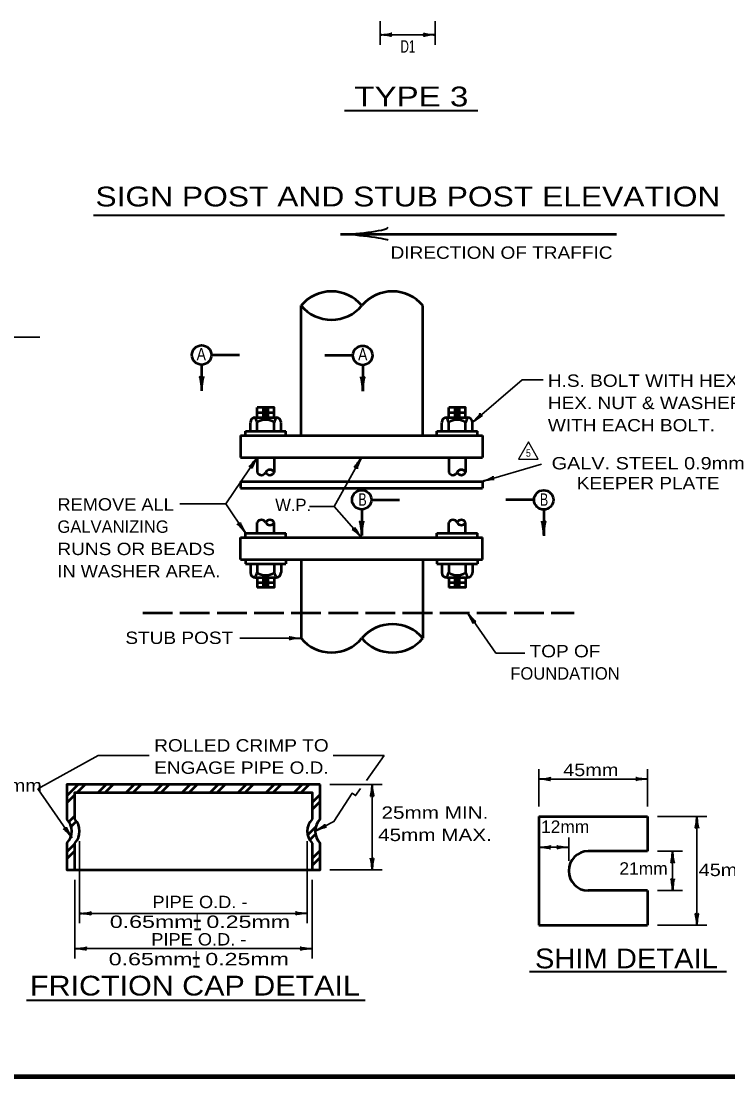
# Model space of a CAD drawing. Extents: x 11 to 867, y -284 to 260.
# Drawn here: x 258 to 429.3, y -272.1 to -16.1 of the extents above; entities that cross this region are included whole.
import ezdxf
from ezdxf.enums import TextEntityAlignment as Align

# ---------------------------------------------------------------- set-up
doc = ezdxf.new("R2010")
doc.units = 0
doc.header["$LTSCALE"] = 1.2
doc.linetypes.add('LONG_DASHED', pattern=[7.5, 6, -1.5])
doc.layers.add('1', color=7, linetype='Continuous', lineweight=53)

msp = doc.modelspace()

# ---------------------------------------------------------------- linework, layer by layer
at = {"layer": '1', "lineweight": 35}
for p, q in [((345.013, -16.126), (345.013, -21.85)), ((358.377, -16.126), (358.377, -21.85)), ((345.013, -19.45), (358.377, -19.45)), ((232.558, -92.754), (262.538, -92.754)), ((367.425, -113.403), (379.445, -103.077)), ((379.445, -103.077), (384.523, -103.077)), ((369.825, -127.715), (384.143, -123.529)), ((307.595, -133.179), (296.457, -133.179)), ((333.905, -133.811), (327.875, -133.811)), ((366.273, -159.583), (373.101, -169.399)), ((325.855, -165.759), (311.025, -165.759)), ((373.101, -169.399), (380.141, -169.399)), ((262.06, -202.238), (276.645, -194.196)), ((276.645, -194.196), (289.043, -194.196)), ((333.644, -194.196), (345.983, -194.196)), ((341.7, -200.214), (345.983, -194.196)), ((383.486, -206.545), (383.486, -197.489)), ((409.886, -206.545), (409.886, -197.489)), ((332.874, -201.194), (345.502, -201.194)), ((343.102, -201.194), (343.102, -221.938)), ((383.486, -199.889), (409.886, -199.889)), ((270.264, -214.108), (262.06, -202.238)), ((412.286, -208.945), (424.216, -208.945)), ((421.816, -208.945), (421.816, -235.345)), ((272.182, -214.926), (272.182, -234.868)), ((327.382, -214.926), (327.382, -234.868)), ((390.758, -219.745), (390.758, -214.039)), ((390.758, -216.439), (383.486, -216.439)), ((412.286, -217.345), (418.336, -217.345)), ((415.936, -217.345), (415.936, -226.945)), ((332.874, -221.938), (345.502, -221.938)), ((271.01, -224.338), (271.01, -243.414)), ((328.554, -224.338), (328.554, -243.414)), ((412.286, -226.945), (418.336, -226.945)), ((272.182, -232.468), (327.382, -232.468)), ((412.286, -235.345), (424.216, -235.345)), ((271.01, -241.014), (328.554, -241.014))]:
    msp.add_line(p, q, dxfattribs=at)
at = {"layer": '1', "lineweight": 40}
for p, q in [((336.358, -37.837), (368.69, -37.837)), ((275.564, -63.195), (428.48, -63.195)), ((381.209, -246.561), (428.965, -246.561)), ((259.342, -253.484), (341.423, -253.484))]:
    msp.add_line(p, q, dxfattribs=at)
at = {"layer": '1'}
for p, q in [((335.435, -67.761), (402.333, -67.761)), ((325.855, -116.557), (325.855, -85.095)), ((355.407, -116.557), (355.407, -85.095)), ((304.117, -97.074), (310.933, -97.074)), ((338.457, -97.166), (331.641, -97.166)), ((301.769, -99.423), (301.769, -105.758)), ((340.804, -99.516), (340.804, -105.851)), ((314.769, -112.203), (319.809, -112.203)), ((315.249, -111.003), (319.329, -111.003)), ((316.449, -110.403), (318.129, -110.403)), ((316.449, -111.603), (318.129, -111.603)), ((361.185, -112.203), (366.225, -112.203)), ((361.665, -111.003), (365.745, -111.003)), ((362.865, -110.403), (364.545, -110.403)), ((362.865, -111.603), (364.545, -111.603)), ((313.569, -115.533), (313.569, -113.403)), ((315.249, -115.533), (315.249, -113.403)), ((319.329, -115.533), (319.329, -113.403)), ((321.009, -115.533), (321.009, -113.403)), ((359.985, -115.533), (359.985, -113.403)), ((361.665, -115.533), (361.665, -113.403)), ((365.745, -115.533), (365.745, -113.403)), ((367.425, -115.533), (367.425, -113.403)), ((311.169, -116.557), (369.825, -116.557)), ((311.169, -116.557), (311.169, -121.937)), ((312.369, -115.533), (322.209, -115.533)), ((312.369, -116.557), (312.369, -115.533)), ((322.209, -116.557), (322.209, -115.533)), ((358.785, -115.533), (368.625, -115.533)), ((358.785, -116.557), (358.785, -115.533)), ((368.625, -116.557), (368.625, -115.533)), ((369.825, -116.557), (369.825, -121.937)), ((311.169, -121.937), (369.825, -121.937)), ((315.249, -121.937), (315.249, -125.537)), ((319.329, -121.937), (319.329, -125.537)), ((361.665, -121.937), (361.665, -125.537)), ((365.745, -121.937), (365.745, -125.537)), ((311.169, -127.715), (369.825, -127.715)), ((311.169, -127.715), (311.169, -129.341)), ((369.825, -127.715), (369.825, -129.341)), ((311.169, -129.341), (369.825, -129.341)), ((342.921, -132.169), (349.737, -132.169)), ((382.345, -132.209), (375.529, -132.209)), ((340.573, -134.519), (340.573, -140.853)), ((384.693, -134.559), (384.693, -140.894)), ((315.249, -140.269), (315.249, -137.693)), ((319.329, -140.269), (319.329, -137.693)), ((361.665, -140.269), (361.665, -137.693)), ((365.745, -140.269), (365.745, -137.693)), ((312.369, -140.269), (322.209, -140.269)), ((312.369, -141.293), (312.369, -140.269)), ((322.209, -141.293), (322.209, -140.269)), ((358.785, -140.269), (368.625, -140.269)), ((358.785, -141.293), (358.785, -140.269)), ((368.625, -141.293), (368.625, -140.269)), ((311.169, -141.293), (369.825, -141.293)), ((311.169, -146.673), (311.169, -141.293)), ((369.825, -146.673), (369.825, -141.293)), ((311.169, -146.673), (369.825, -146.673)), ((312.369, -146.673), (312.369, -147.697)), ((312.369, -147.697), (322.209, -147.697)), ((313.569, -147.697), (313.569, -149.827)), ((315.249, -147.697), (315.249, -149.827)), ((319.329, -147.697), (319.329, -149.827)), ((321.009, -147.697), (321.009, -149.827)), ((322.209, -146.673), (322.209, -147.697)), ((325.855, -146.673), (325.855, -165.759)), ((355.407, -146.673), (355.407, -165.759)), ((358.785, -146.673), (358.785, -147.697)), ((358.785, -147.697), (368.625, -147.697)), ((359.985, -147.697), (359.985, -149.827)), ((361.665, -147.697), (361.665, -149.827)), ((365.745, -147.697), (365.745, -149.827)), ((367.425, -147.697), (367.425, -149.827)), ((368.625, -146.673), (368.625, -147.697)), ((314.769, -151.027), (319.809, -151.027)), ((315.249, -152.227), (319.329, -152.227)), ((316.449, -151.627), (318.129, -151.627)), ((316.449, -152.827), (318.129, -152.827)), ((361.185, -151.027), (366.225, -151.027)), ((361.665, -152.227), (365.745, -152.227)), ((362.865, -151.627), (364.545, -151.627)), ((362.865, -152.827), (364.545, -152.827)), ((269.09, -203.942), (271.838, -201.194)), ((271.615, -203.114), (273.535, -201.194)), ((276.706, -203.114), (278.626, -201.194)), ((278.404, -203.114), (280.324, -201.194)), ((283.495, -203.114), (285.415, -201.194)), ((285.192, -203.114), (287.112, -201.194)), ((290.283, -203.114), (292.203, -201.194)), ((291.98, -203.114), (293.9, -201.194)), ((297.071, -203.114), (298.991, -201.194)), ((298.768, -203.114), (300.688, -201.194)), ((303.859, -203.114), (305.779, -201.194)), ((305.556, -203.114), (307.476, -201.194)), ((310.648, -203.114), (312.567, -201.194)), ((312.345, -203.114), (314.265, -201.194)), ((317.436, -203.114), (319.356, -201.194)), ((319.133, -203.114), (321.053, -201.194)), ((324.224, -203.114), (326.144, -201.194)), ((325.921, -203.114), (327.841, -201.194)), ((330.474, -209.586), (330.474, -201.194)), ((269.09, -205.639), (271.01, -203.719)), ((328.554, -205.572), (330.474, -203.652)), ((328.554, -207.269), (330.474, -205.349)), ((269.585, -210.235), (271.01, -208.811)), ((383.486, -208.945), (409.886, -208.945)), ((383.486, -208.945), (383.486, -235.345)), ((409.886, -208.945), (409.886, -217.345)), ((270.104, -211.413), (271.42, -210.097)), ((327.489, -213.425), (329.444, -211.471)), ((327.961, -214.651), (329.366, -213.246)), ((269.09, -217.519), (271.01, -215.599)), ((269.09, -219.216), (271.01, -217.296)), ((328.554, -219.149), (330.474, -217.229)), ((409.886, -217.345), (395.498, -217.345)), ((328.554, -220.846), (330.474, -218.926)), ((271.01, -221.938), (328.554, -221.938)), ((409.886, -226.945), (395.498, -226.945)), ((409.886, -226.945), (409.886, -235.345)), ((383.486, -235.345), (409.886, -235.345))]:
    msp.add_line(p, q, dxfattribs=at)
at = {"layer": '1', "linetype": 'LONG_DASHED'}
msp.add_line((287.495, -159.609), (392.105, -159.609), dxfattribs=at)
at = {"layer": '1', "lineweight": 158}
msp.add_line((860.008, -272.101), (68.408, -272.101), dxfattribs=at)
at = {"layer": '1'}
for points in [[(319.329, -112.203), (319.329, -109.803), (315.249, -109.803)], [(315.249, -112.203), (315.249, -111.003), (315.249, -109.803)], [(365.745, -112.203), (365.745, -109.803), (361.665, -109.803)], [(361.665, -112.203), (361.665, -111.003), (361.665, -109.803)], [(319.329, -151.027), (319.329, -153.427), (315.249, -153.427)], [(315.249, -151.027), (315.249, -152.227), (315.249, -153.427)], [(365.745, -151.027), (365.745, -153.427), (361.665, -153.427)], [(361.665, -151.027), (361.665, -152.227), (361.665, -153.427)], [(330.474, -201.194), (269.09, -201.194), (269.09, -209.586)], [(271.01, -209.586), (271.01, -203.114), (328.554, -203.114), (328.554, -209.586)], [(269.09, -215.466), (269.09, -221.938), (271.01, -221.938), (271.01, -215.466)], [(328.554, -215.466), (328.554, -221.938), (330.474, -221.938), (330.474, -215.466)]]:
    msp.add_lwpolyline(points, dxfattribs=at)
at = {"layer": '1', "lineweight": 25}
msp.add_lwpolyline([(380.978, -118.162), (378.578, -122.319), (383.378, -122.319)], close=True, dxfattribs=at)
at = {"layer": '1', "lineweight": 35}
for points in [[(315.249, -121.937), (307.595, -133.179), (312.369, -140.269)], [(340.497, -121.937), (333.905, -133.811), (340.497, -141.293)], [(329.302, -212.526), (333.85, -210.192), (338.238, -203.324), (339.088, -203.89), (340.308, -202.172)]]:
    msp.add_lwpolyline(points, dxfattribs=at)
at = {"layer": '1'}
for centre in [(301.768, -97.075), (340.805, -97.167), (340.572, -132.17), (384.694, -132.21)]:
    msp.add_circle(centre, 2.349, dxfattribs=at)
for centre, radius, start, end in [((333.243, -91.313), 9.656, 40.08466, 139.91534), ((348.019, -91.313), 9.656, 40.08466, 139.91534), ((333.243, -78.877), 9.656, 220.08466, 319.91534), ((314.815, -113.449), 1.247, 92.13194, 177.86806), ((301.279, -118.295), 14.802, 19.29918, 24.30364), ((333.299, -118.295), 14.802, 155.69636, 160.70082), ((319.762, -113.449), 1.247, 2.13194, 87.86806), ((361.231, -113.449), 1.247, 92.13194, 177.86806), ((347.695, -118.295), 14.802, 19.29918, 24.30364), ((379.715, -118.295), 14.802, 155.69636, 160.70082), ((366.178, -113.449), 1.247, 2.13194, 87.86806), ((317.289, -116.372), 3.602, 55.5053, 124.4947), ((363.705, -116.372), 3.602, 55.5053, 124.4947), ((318.309, -126.023), 1.13, 25.46796, 154.53204), ((364.725, -126.023), 1.13, 25.46796, 154.53204), ((316.269, -125.051), 1.13, 205.46796, 334.53204), ((318.309, -125.051), 1.13, 205.46796, 334.53204), ((362.685, -125.051), 1.13, 205.46796, 334.53204), ((364.725, -125.051), 1.13, 205.46796, 334.53204), ((316.269, -138.179), 1.13, 25.46796, 154.53204), ((318.309, -138.179), 1.13, 25.46796, 154.53204), ((318.309, -137.207), 1.13, 205.46796, 334.53204), ((362.685, -138.179), 1.13, 25.46796, 154.53204), ((364.725, -138.179), 1.13, 25.46796, 154.53204), ((364.725, -137.207), 1.13, 205.46796, 334.53204), ((314.815, -149.781), 1.247, 182.13194, 267.86806), ((301.279, -144.935), 14.802, 335.69636, 340.70082), ((317.289, -146.858), 3.602, 235.5053, 304.4947), ((333.299, -144.935), 14.802, 199.29918, 204.30364), ((319.762, -149.781), 1.247, 272.13194, 357.86806), ((361.231, -149.781), 1.247, 182.13194, 267.86806), ((347.695, -144.935), 14.802, 335.69636, 340.70082), ((363.705, -146.858), 3.602, 235.5053, 304.4947), ((379.715, -144.935), 14.802, 199.29918, 204.30364), ((366.178, -149.781), 1.247, 272.13194, 357.86806), ((348.019, -171.977), 9.656, 40.08466, 139.91534), ((333.243, -159.541), 9.656, 220.08466, 319.91534), ((348.019, -159.541), 9.656, 220.08466, 319.91534), ((265.99, -212.526), 4.272, 316.51802, 43.48198), ((267.91, -212.526), 4.272, 316.51802, 43.48198), ((331.654, -212.526), 4.272, 136.51802, 223.48198), ((333.574, -212.526), 4.272, 136.51802, 223.48198), ((395.557, -222.145), 4.8, 90.71094, 269.28906)]:
    msp.add_arc(centre, radius, start, end, dxfattribs=at)
at = {"layer": '1', "lineweight": 40}
for centre, major_axis, ratio, start_param, end_param in [((346.133, -19.661), (-1.756, 0.176), 0.07063, 3.1407148, 5.41811), ((346.133, -19.661), (-1.756, 0.176), 0.07063, 3.1407148, 5.41811), ((346.104, -19.173), (-1.786, -0.156), 0.122415, 0.8963533, 3.1415927), ((346.104, -19.173), (-1.786, -0.156), 0.122415, 0.8963533, 3.1415927), ((357.286, -19.726), (1.786, 0.156), 0.122415, 0.8963533, 3.1415927), ((357.256, -19.238), (1.756, -0.176), 0.07063, 3.1407148, 5.41811), ((339.835, -66.688), (-7.143, -0.625), 0.122415, 0.8963533, 3.1415927), ((339.953, -68.639), (-7.026, 0.703), 0.07063, 3.1407148, 5.41811), ((301.434, -104.432), (0.19, -2.17), 0.122415, 0.8963533, 3.1415927), ((302.026, -104.397), (-0.213, -2.134), 0.07063, 3.1407148, 5.41811), ((340.547, -104.489), (0.213, -2.134), 0.07063, 0.8650754, 3.1424706), ((341.14, -104.525), (-0.19, -2.17), 0.122415, 3.1415927, 5.386832), ((368.072, -112.482), (-1.253, -1.282), 0.122415, 0.8963533, 3.1415927), ((368.072, -112.482), (-1.253, -1.282), 0.122415, 0.8963533, 3.1415927), ((368.413, -112.833), (-1.447, -1.011), 0.07063, 3.1407148, 5.41811), ((368.413, -112.833), (-1.447, -1.011), 0.07063, 3.1407148, 5.41811), ((314.443, -122.744), (1.134, 1.353), 0.07063, 3.1407148, 5.41811), ((314.443, -122.744), (1.134, 1.353), 0.07063, 3.1407148, 5.41811), ((314.863, -122.994), (0.876, 1.564), 0.122415, 0.8963533, 3.1415927), ((314.863, -122.994), (0.876, 1.564), 0.122415, 0.8963533, 3.1415927), ((339.768, -122.814), (1.006, 1.45), 0.07063, 3.1407148, 5.41811), ((339.768, -122.814), (1.006, 1.45), 0.07063, 3.1407148, 5.41811), ((340.209, -123.025), (0.73, 1.637), 0.122415, 0.8963533, 3.1415927), ((340.209, -123.025), (0.73, 1.637), 0.122415, 0.8963533, 3.1415927), ((370.795, -127.143), (-1.67, -0.651), 0.122415, 0.8963533, 3.1415927), ((370.96, -127.604), (-1.735, -0.324), 0.07063, 3.1407148, 5.41811), ((311.53, -139.518), (1.127, -1.394), 0.122415, 0.8963533, 3.1415927), ((311.918, -139.221), (0.835, -1.555), 0.07063, 3.1407148, 5.41811), ((340.238, -139.528), (0.19, -2.17), 0.122415, 0.8963533, 3.1415927), ((340.83, -139.492), (-0.213, -2.134), 0.07063, 3.1407148, 5.41811), ((384.436, -139.532), (0.213, -2.134), 0.07063, 0.8650754, 3.1424706), ((385.028, -139.568), (-0.19, -2.17), 0.122415, 3.1415927, 5.386832), ((339.568, -140.657), (1.298, -1.237), 0.122415, 0.8963533, 3.1415927), ((339.915, -140.312), (1.029, -1.434), 0.07063, 3.1407148, 5.41811), ((366.739, -160.624), (-0.859, 1.542), 0.07063, 3.1407148, 5.41811), ((367.123, -160.321), (-1.148, 1.377), 0.122415, 0.8963533, 3.1415927), ((324.764, -166.035), (1.786, 0.156), 0.122415, 0.8963533, 3.1415927), ((324.734, -165.547), (1.756, -0.176), 0.07063, 3.1407148, 5.41811), ((384.577, -199.613), (-1.786, -0.156), 0.122415, 0.8963533, 3.1415927), ((384.577, -199.613), (-1.786, -0.156), 0.122415, 0.8963533, 3.1415927), ((408.765, -199.678), (1.756, -0.176), 0.07063, 3.1407148, 5.41811), ((342.89, -202.314), (0.176, 1.756), 0.07063, 3.1407148, 5.41811), ((342.89, -202.314), (0.176, 1.756), 0.07063, 3.1407148, 5.41811), ((343.378, -202.285), (-0.156, 1.786), 0.122415, 0.8963533, 3.1415927), ((343.378, -202.285), (-0.156, 1.786), 0.122415, 0.8963533, 3.1415927), ((384.606, -200.101), (-1.756, 0.176), 0.07063, 3.1407148, 5.41811), ((384.606, -200.101), (-1.756, 0.176), 0.07063, 3.1407148, 5.41811), ((408.795, -200.166), (1.786, 0.156), 0.122415, 0.8963533, 3.1415927), ((421.604, -210.066), (0.176, 1.756), 0.07063, 3.1407148, 5.41811), ((421.604, -210.066), (0.176, 1.756), 0.07063, 3.1407148, 5.41811), ((422.092, -210.037), (-0.156, 1.786), 0.122415, 0.8963533, 3.1415927), ((422.092, -210.037), (-0.156, 1.786), 0.122415, 0.8963533, 3.1415927), ((269.416, -213.367), (1.144, -1.38), 0.122415, 0.8963533, 3.1415927), ((269.801, -213.066), (0.854, -1.545), 0.07063, 3.1407148, 5.41811), ((330.146, -211.782), (-1.517, -0.954), 0.122415, 0.8963533, 3.1415927), ((330.395, -212.203), (-1.643, -0.646), 0.07063, 3.1407148, 5.41811), ((384.606, -216.651), (-1.756, 0.176), 0.07063, 3.1407148, 5.41811), ((384.606, -216.651), (-1.756, 0.176), 0.07063, 3.1407148, 5.41811), ((384.577, -216.163), (-1.786, -0.156), 0.122415, 0.8963533, 3.1415927), ((384.577, -216.163), (-1.786, -0.156), 0.122415, 0.8963533, 3.1415927), ((389.667, -216.716), (1.786, 0.156), 0.122415, 0.8963533, 3.1415927), ((389.637, -216.228), (1.756, -0.176), 0.07063, 3.1407148, 5.41811), ((415.724, -218.466), (0.176, 1.756), 0.07063, 3.1407148, 5.41811), ((415.724, -218.466), (0.176, 1.756), 0.07063, 3.1407148, 5.41811), ((416.212, -218.437), (-0.156, 1.786), 0.122415, 0.8963533, 3.1415927), ((416.212, -218.437), (-0.156, 1.786), 0.122415, 0.8963533, 3.1415927), ((342.826, -220.847), (0.156, -1.786), 0.122415, 0.8963533, 3.1415927), ((343.313, -220.817), (-0.176, -1.756), 0.07063, 3.1407148, 5.41811), ((415.659, -225.854), (0.156, -1.786), 0.122415, 0.8963533, 3.1415927), ((415.659, -225.854), (0.156, -1.786), 0.122415, 0.8963533, 3.1415927), ((416.147, -225.825), (-0.176, -1.756), 0.07063, 3.1407148, 5.41811), ((416.147, -225.825), (-0.176, -1.756), 0.07063, 3.1407148, 5.41811), ((273.302, -232.68), (-1.756, 0.176), 0.07063, 3.1407148, 5.41811), ((273.302, -232.68), (-1.756, 0.176), 0.07063, 3.1407148, 5.41811), ((273.273, -232.192), (-1.786, -0.156), 0.122415, 0.8963533, 3.1415927), ((273.273, -232.192), (-1.786, -0.156), 0.122415, 0.8963533, 3.1415927), ((326.291, -232.744), (1.786, 0.156), 0.122415, 0.8963533, 3.1415927), ((326.291, -232.744), (1.786, 0.156), 0.122415, 0.8963533, 3.1415927), ((326.261, -232.256), (1.756, -0.176), 0.07063, 3.1407148, 5.41811), ((326.261, -232.256), (1.756, -0.176), 0.07063, 3.1407148, 5.41811), ((421.539, -234.254), (0.156, -1.786), 0.122415, 0.8963533, 3.1415927), ((422.027, -234.225), (-0.176, -1.756), 0.07063, 3.1407148, 5.41811), ((272.101, -240.738), (-1.786, -0.156), 0.122415, 0.8963533, 3.1415927), ((272.13, -241.226), (-1.756, 0.176), 0.07063, 3.1407148, 5.41811), ((327.463, -241.29), (1.786, 0.156), 0.122415, 0.8963533, 3.1415927), ((327.463, -241.29), (1.786, 0.156), 0.122415, 0.8963533, 3.1415927), ((327.433, -240.802), (1.756, -0.176), 0.07063, 3.1407148, 5.41811), ((327.433, -240.802), (1.756, -0.176), 0.07063, 3.1407148, 5.41811)]:
    msp.add_ellipse(centre, major_axis=major_axis, ratio=ratio, start_param=start_param, end_param=end_param, dxfattribs=at)

# ---------------------------------------------------------------- texts
at = {"layer": '1'}
for s, height, width, p in [('D1', 3, 0.7, (351.777, -23.753)), ('TYPE 3', 4.8, 1.25, (352.596, -36.804)), ('SIGN POST AND STUB POST ELEVATION', 4.8, 1.2, (351.767, -61.058)), ('DIRECTION OF TRAFFIC', 3, 1.15, (374.466, -73.755)), ('A', 3, 0.85, (301.675, -98.39)), ('A', 3, 0.85, (340.822, -98.401)), ('5', 1.8, 0.9, (380.978, -121.744)), ('GALV. STEEL 0.9mm', 3, 1.2, (410.019, -124.818)), ('KEEPER PLATE', 3, 1.15, (410.019, -129.618)), ('B', 3, 0.75, (340.768, -133.621)), ('B', 3, 0.75, (384.783, -133.632)), ('STUB POST', 3, 1.15, (296.344, -167.143)), ('TOP OF', 3, 1.15, (389.854, -170.382)), ('45mm', 3, 1.2, (396.105, -199.174)), ('DEPTH  1.3mm', 3, 1.2, (246.173, -202.93)), ('25mm MIN.', 3, 1.25, (358.324, -209.531)), ('12mm', 3, 1.05, (389.891, -212.938)), ('45mm MAX.', 3, 1.25, (358.324, -214.931)), ('21mm', 3, 1.05, (408.889, -223.061)), ('45mm', 3, 1.2, (428.953, -223.416)), ('PIPE O.D. -', 3, 1.1, (301.355, -231.191)), ('+', 4.8, 0.55, (300.68, -236.581)), ('0.65mm  0.25mm', 3, 1.4, (301.355, -235.991)), ('PIPE O.D. -', 3, 1.1, (301.089, -240.248)), ('0.65mm  0.25mm', 3, 1.4, (301.089, -245.048)), ('+', 4.8, 0.55, (300.413, -245.638)), ('SHIM DETAIL', 4.8, 1.1, (404.735, -245.787)), ('FRICTION CAP DETAIL', 4.8, 1.15, (300.132, -252.38))]:
    msp.add_text(s, height=height, dxfattribs=dict(at, width=width)).set_placement(p, align=Align.CENTER)
for s, width, p in [('H.S. BOLT WITH HEX. HD.,', 1.15, (385.698, -104.799)), ('HEX. NUT & WASHERS', 1.15, (385.698, -110.199)), ('WITH EACH BOLT.', 1.15, (385.698, -115.599)), ('REMOVE ALL', 1.1, (266.807, -134.791)), ('RUNS OR BEADS', 1.15, (266.807, -145.591)), ('IN WASHER AREA.', 1.1, (266.807, -150.991)), ('ROLLED CRIMP TO', 1.15, (290.265, -193.224)), ('ENGAGE PIPE O.D.', 1.15, (290.265, -198.624))]:
    msp.add_text(s, height=3, dxfattribs=dict(at, width=width)).set_placement(p)
for s, height, p in [('W.P.', 3, (323.952, -134.924)), ('FOUNDATION', 3, (389.854, -175.782)), ('-', 4.8, (300.798, -238.184)), ('-', 4.8, (300.532, -247.241))]:
    msp.add_text(s, height=height, dxfattribs=at).set_placement(p, align=Align.CENTER)
msp.add_text('GALVANIZING', height=3, dxfattribs=at).set_placement((266.807, -140.191))

doc.saveas('drawing.dxf')
